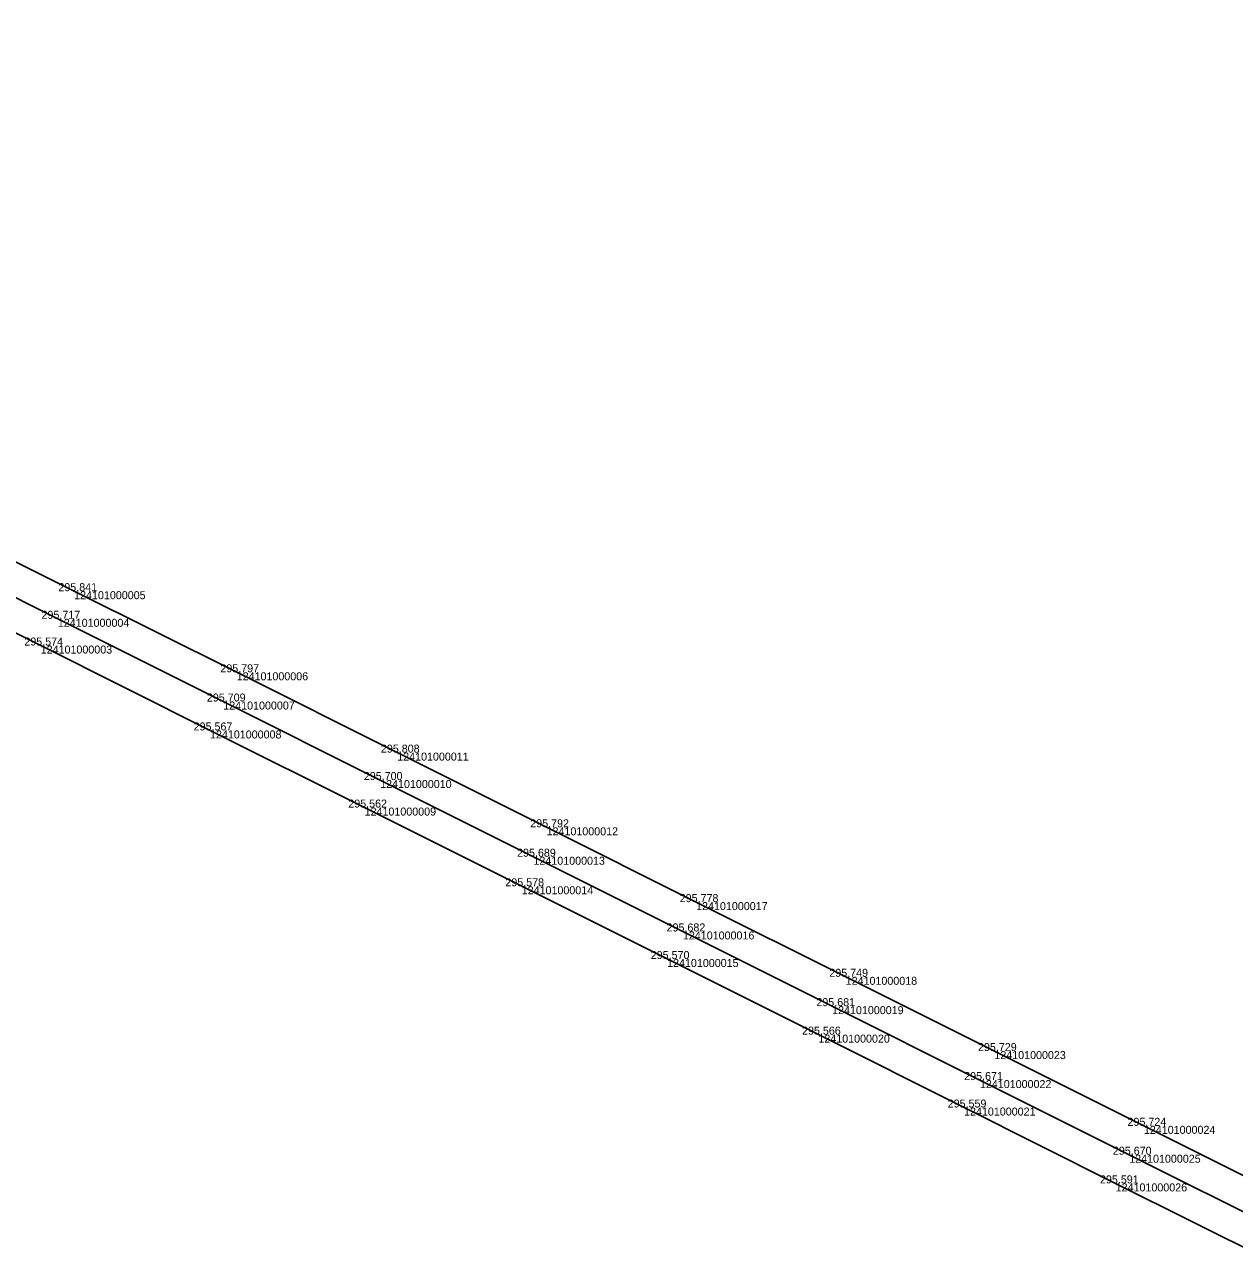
# Model space of a CAD drawing. Extents: x -616949 to -607976, y -1164436 to -1159224.
# Drawn here: x -613357.3 to -613176.1, y -1161560.9 to -1161375.7 of the extents above; entities that cross this region are included whole.
import ezdxf

# ---------------------------------------------------------------- set-up
doc = ezdxf.new("R2010")
doc.units = 0
for name, color, linetype in [('Vrstva 1', 7, 'Continuous'), ('Vrstva 60', 7, 'Continuous'), ('Vrstva 61', 7, 'Continuous')]:
    doc.layers.add(name, color=color, linetype=linetype)

msp = doc.modelspace()

# ---------------------------------------------------------------- linework, layer by layer
at = {"layer": 'Vrstva 1'}
for points in [[(-613170.83, -1161560.95), (-613193.86, -1161549.42), (-613216.58, -1161538.05), (-613238.41, -1161527.12), (-613261.08, -1161515.78), (-613282.87, -1161504.88), (-613306.41, -1161493.08), (-613329.58, -1161481.52), (-613354.95, -1161468.79), (-613375.86, -1161458.34), (-613397.09, -1161447.7), (-613423.08, -1161434.66), (-613445.18, -1161423.56), (-613454.31, -1161418.97), (-613455.76, -1161418.24), (-613459.55, -1161416.34), (-613467.93, -1161412.15), (-613475.56, -1161408.23), (-613486.6, -1161402.08), (-613495.53, -1161396.7), (-613502.97, -1161391.95), (-613517.07, -1161383.03), (-613530.57, -1161376.42), (-613531.97, -1161375.72)], [(-613169.01, -1161556.54), (-613191.83, -1161545.12), (-613214.2, -1161533.93), (-613236.35, -1161522.85), (-613258.71, -1161511.65), (-613281.11, -1161500.45), (-613304.08, -1161488.95), (-613327.59, -1161477.18), (-613352.38, -1161464.78), (-613374.13, -1161453.9), (-613400.96, -1161440.47), (-613420.84, -1161430.52), (-613443.07, -1161419.4), (-613460.41, -1161410.77), (-613461.85, -1161410.06), (-613466.23, -1161407.9), (-613484.35, -1161399.03), (-613502.11, -1161390.35), (-613517.07, -1161383.03), (-613530.57, -1161376.42), (-613531.97, -1161375.72)], [(-613166.98, -1161552.11), (-613189.63, -1161540.79), (-613212.04, -1161529.58), (-613234.32, -1161518.45), (-613256.73, -1161507.25), (-613279.14, -1161496.04), (-613301.52, -1161484.84), (-613325.58, -1161472.8), (-613349.94, -1161460.64), (-613371.44, -1161449.88)]]:
    msp.add_lwpolyline(points, dxfattribs=at)
at = {"layer": 'Vrstva 60'}
for p, q in [((-613349.94, -1161460.64), (-613349.94, -1161460.64)), ((-613352.38, -1161464.78), (-613352.38, -1161464.78)), ((-613354.95, -1161468.79), (-613354.95, -1161468.79)), ((-613325.58, -1161472.8), (-613325.58, -1161472.8)), ((-613327.59, -1161477.18), (-613327.59, -1161477.18)), ((-613329.58, -1161481.52), (-613329.58, -1161481.52)), ((-613301.52, -1161484.84), (-613301.52, -1161484.84)), ((-613304.08, -1161488.95), (-613304.08, -1161488.95)), ((-613306.41, -1161493.08), (-613306.41, -1161493.08)), ((-613279.14, -1161496.04), (-613279.14, -1161496.04)), ((-613281.11, -1161500.45), (-613281.11, -1161500.45)), ((-613282.87, -1161504.88), (-613282.87, -1161504.88)), ((-613256.73, -1161507.25), (-613256.73, -1161507.25)), ((-613258.71, -1161511.65), (-613258.71, -1161511.65)), ((-613261.08, -1161515.78), (-613261.08, -1161515.78)), ((-613234.32, -1161518.45), (-613234.32, -1161518.45)), ((-613236.35, -1161522.85), (-613236.35, -1161522.85)), ((-613238.41, -1161527.12), (-613238.41, -1161527.12)), ((-613212.04, -1161529.58), (-613212.04, -1161529.58)), ((-613214.2, -1161533.93), (-613214.2, -1161533.93)), ((-613216.58, -1161538.05), (-613216.58, -1161538.05)), ((-613189.63, -1161540.79), (-613189.63, -1161540.79)), ((-613191.83, -1161545.12), (-613191.83, -1161545.12)), ((-613193.86, -1161549.42), (-613193.86, -1161549.42))]:
    msp.add_line(p, q, dxfattribs=at)

# ---------------------------------------------------------------- texts
for s, p in [('124101000005', (-613349.94, -1161461.84)), ('124101000004', (-613352.38, -1161465.98)), ('124101000003', (-613354.95, -1161469.99)), ('124101000006', (-613325.58, -1161474)), ('124101000007', (-613327.59, -1161478.38)), ('124101000008', (-613329.58, -1161482.72)), ('124101000011', (-613301.52, -1161486.04)), ('124101000010', (-613304.08, -1161490.15)), ('124101000009', (-613306.41, -1161494.28)), ('124101000012', (-613279.14, -1161497.24)), ('124101000013', (-613281.11, -1161501.65)), ('124101000014', (-613282.87, -1161506.08)), ('124101000017', (-613256.73, -1161508.45)), ('124101000016', (-613258.71, -1161512.85)), ('124101000015', (-613261.08, -1161516.98)), ('124101000018', (-613234.32, -1161519.65)), ('124101000019', (-613236.35, -1161524.05)), ('124101000020', (-613238.41, -1161528.32)), ('124101000023', (-613212.04, -1161530.78)), ('124101000022', (-613214.2, -1161535.13)), ('124101000021', (-613216.58, -1161539.25)), ('124101000024', (-613189.63, -1161541.99)), ('124101000025', (-613191.83, -1161546.32)), ('124101000026', (-613193.86, -1161550.62))]:
    msp.add_text(s, height=1.2, dxfattribs=at).set_placement(p)
at = {"layer": 'Vrstva 61'}
for s, p in [('295.841', (-613352.3, -1161460.64)), ('295.717', (-613354.83, -1161464.78)), ('295.574', (-613357.4, -1161468.79)), ('295.797', (-613328.03, -1161472.8)), ('295.709', (-613330.05, -1161477.18)), ('295.567', (-613332.03, -1161481.52)), ('295.808', (-613303.97, -1161484.84)), ('295.700', (-613306.53, -1161488.95)), ('295.562', (-613308.86, -1161493.08)), ('295.792', (-613281.59, -1161496.04)), ('295.689', (-613283.56, -1161500.45)), ('295.578', (-613285.32, -1161504.88)), ('295.778', (-613259.19, -1161507.25)), ('295.682', (-613261.16, -1161511.65)), ('295.570', (-613263.53, -1161515.78)), ('295.749', (-613236.77, -1161518.45)), ('295.681', (-613238.71, -1161522.85)), ('295.566', (-613240.86, -1161527.12)), ('295.729', (-613214.49, -1161529.58)), ('295.671', (-613216.56, -1161533.93)), ('295.559', (-613219.03, -1161538.05)), ('295.724', (-613192.08, -1161540.79)), ('295.670', (-613194.28, -1161545.12)), ('295.591', (-613196.21, -1161549.42))]:
    msp.add_text(s, height=1.2, dxfattribs=at).set_placement(p)

doc.saveas('drawing.dxf')
